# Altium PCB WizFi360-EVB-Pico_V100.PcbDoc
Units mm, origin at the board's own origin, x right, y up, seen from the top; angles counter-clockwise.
Board outline 75 x 21 mm, 2 copper layers (Top Layer, Bottom Layer); 60 components, 66 nets, 301 pads, 138 vias.
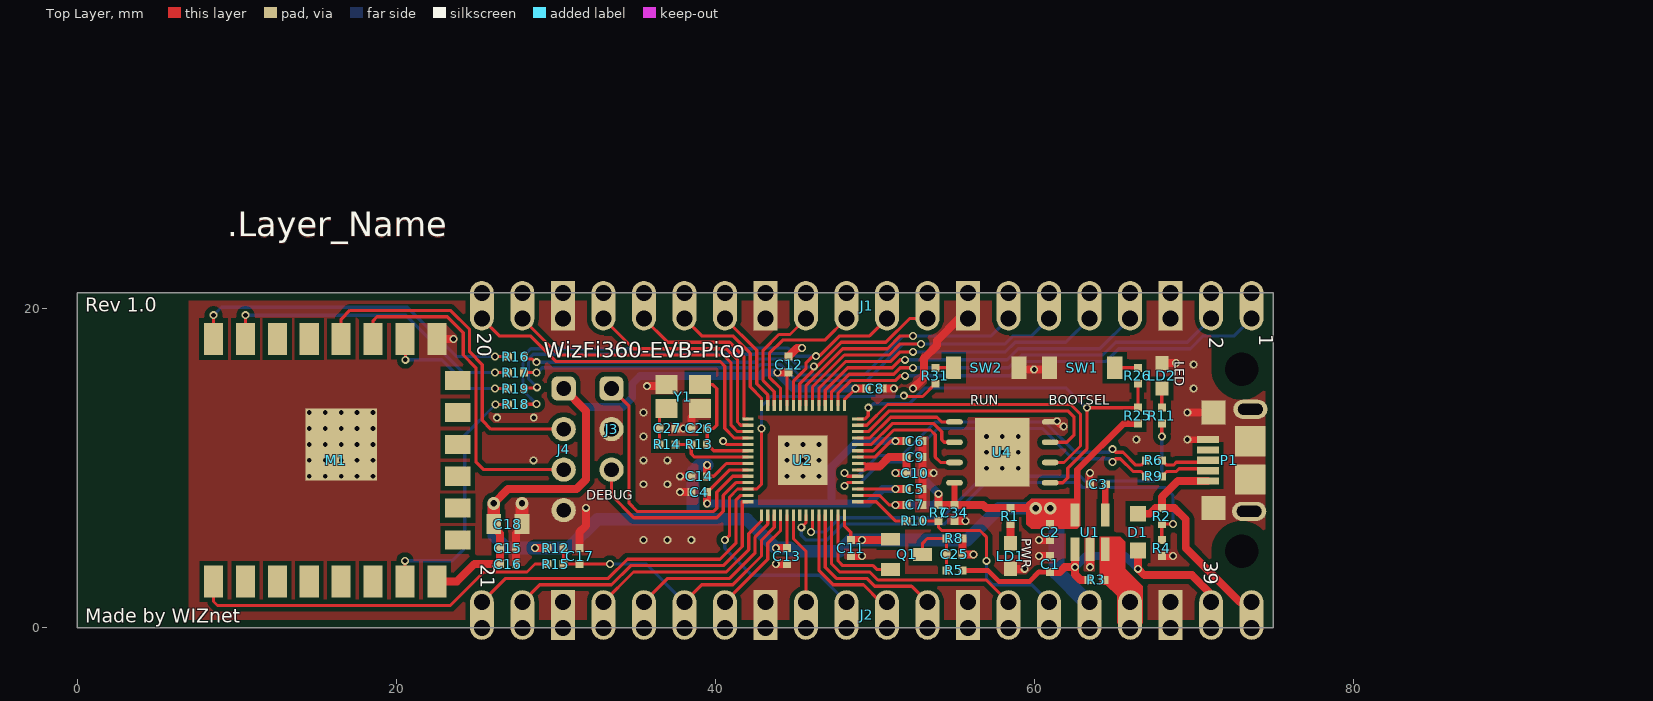
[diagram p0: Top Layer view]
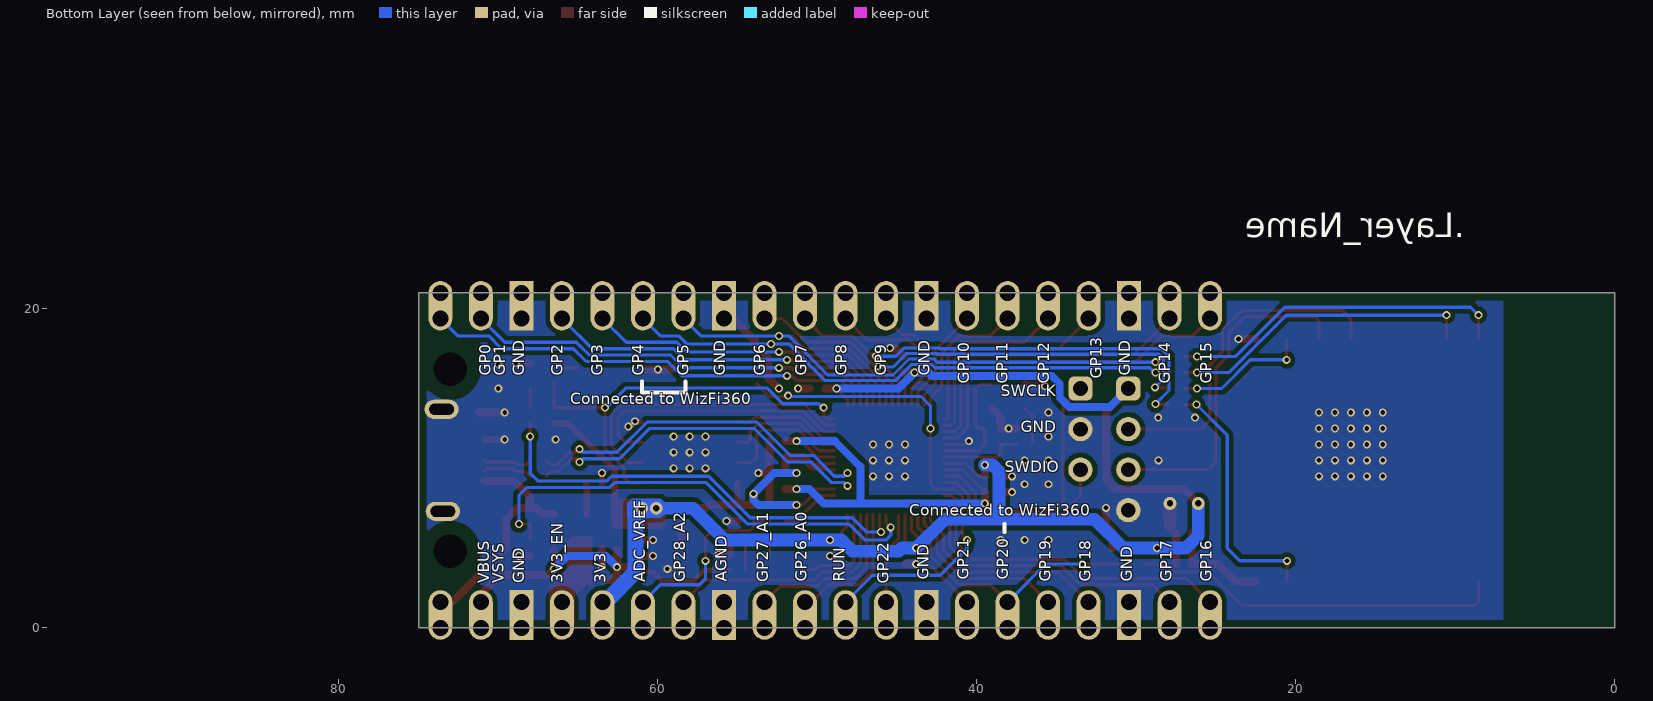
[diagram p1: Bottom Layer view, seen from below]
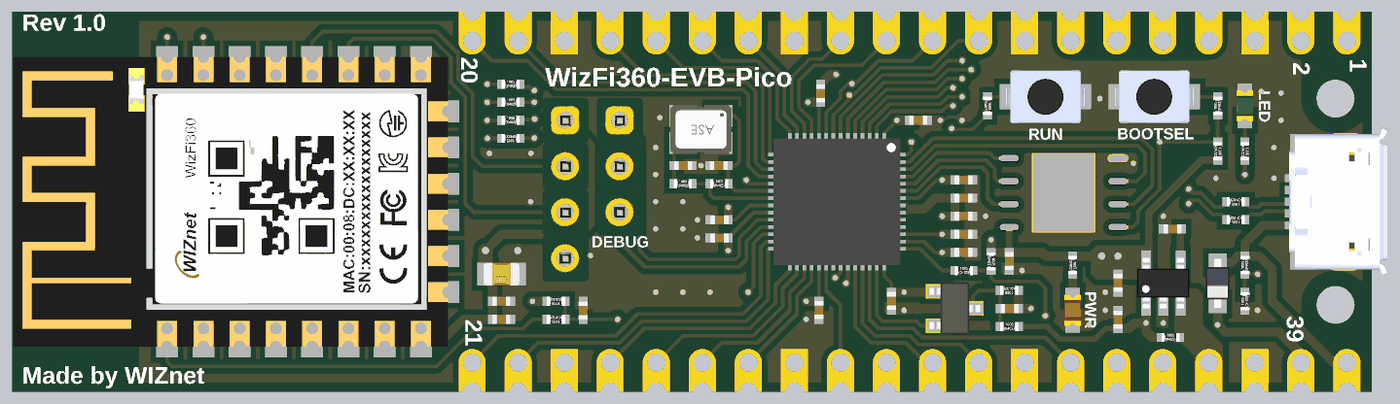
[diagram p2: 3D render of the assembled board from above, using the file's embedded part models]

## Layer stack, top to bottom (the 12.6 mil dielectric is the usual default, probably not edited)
Top Solder: solder mask 0.0102, Solder Resist, Dk 3.5
Top Layer: signal copper 0.0356
Dielectric1: prepreg 0.32, FR-4, Dk 4.8
Bottom Layer: signal copper 0.0356
Bottom Solder: solder mask 0.0102, Solder Resist, Dk 3.5

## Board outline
0,0 75,0 75,21 0,21

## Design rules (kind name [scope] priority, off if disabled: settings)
BoardOutlineClearance [All] p1: gap=0.5 ignorepadtopadclearanceinfootprint=FALSE
Clearance [All] p1: gap=0.15 ignorepadtopadclearanceinfootprint=FALSE except(0.3: Arc-Poly Track-Poly SMDPad-Poly THPad-Poly Via-Poly Fill-Poly Poly-Poly Poly-Region Poly-Text Poly-Hole)
DiffPairsRouting [All] p1: maxlimit=0.2 minlimit=0.2 mostfreqgap=0.2 toplayer_minwidth=0.2 toplayer_maxwidth=0.2 toplayer_prefwidth=0.2 bottomlayer_minwidth=0.2 bottomlayer_maxwidth=0.2 bottomlayer_prefwidth=0.2 maxuncoupledlength=15.24
HoleSize [All] p1: absolutevalues=TRUE maxlimit=4.064 minlimit=0.025 maxpercent=80.000 minpercent=20.000
PlaneClearance [All] p1: clearance=0.3
PlaneConnect [All] p1: planeconnectstyle=Direct reliefexpansion=0.508 reliefentries=4 reliefconductorwidth=0.254 reliefairgap=0.254
PolygonConnect [All] p1: connectstyle=Direct reliefconductorwidth=0.6 reliefentries=4 polygonreliefangle="45 Angle" airgapwidth=0.35
RoutingVias [All] p1: holewidth=0.3 width=0.5 viastyle="Through Hole" minholewidth=0.3 minwidth=0.5 maxholewidth=0.5 maxwidth=0.8
SolderMaskExpansion [All] p1: expansion=0 istentingtop=FALSE
Width [All] p1: maxlimit=2 minlimit=0.1 preferedwidth=0.2 minimp=50.000000 maximp=50.000000 favimp=50.000000
26 further rules are at their usual default settings.

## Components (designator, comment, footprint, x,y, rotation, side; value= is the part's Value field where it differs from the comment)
C1 "1uF" CAP-0402 61,4 r270 top
C2 "1uF" CAP-0402 61,6 r90 top
C3 "0.1uF" CAP-0402 64,9 r0 top
C4 "1uF" CAP-0402 39,8.5 r0 top
C5 "0.1uF" CAP-0402 52.5,8.7 r180 top
C6 "0.1uF" CAP-0402 52.5,11.7 r180 top
C7 "1uF" CAP-0402 52.5,7.7 r180 top
C8 "0.1uF" CAP-0402 50,15 r180 top
C9 "0.1uF" CAP-0402 52.5,10.7 r180 top
C10 "0.1uF" CAP-0402 52.5,9.7 r180 top
C11 "0.1uF" CAP-0402 48.5,5 r90 top
C12 "0.1uF" CAP-0402 44.6,16.5 r270 top
C13 "0.1uF" CAP-0402 44.5,4.5 r90 top
C14 "0.1uF" CAP-0402 39,9.5 r0 top
C15 "0.1uF" CAP-0402 27,5 r180 top
C16 "0.1uF" CAP-0402 27,4 r180 top
C17 "0.1uF" CAP-0402 31.5,4.5 r270 top
C18 "22uF" CAP-0805 27,6.5 r180 top
C25 "0.1uF" CAP-0402 55,4.6 r0 top
C26 "15pF" CAP-0402 39,12.5 r180 top
C27 "15pF" CAP-0402 37,12.5 r0 top
C34 "0.1uF" CAP-0402 55,7.2 r90 top
D1 "BAT60A" SOD-323(1-C,2-A) 66.5,6 r90 top
J1 "2.54mm 1x20 Pin Header DIP" IDC-1X20 73.63,19.39 r180 top
J2 "2.54mm 1x20 Pin Header DIP" IDC-1X20 25.37,1.61 r0 top
J3 "2.54mm 1x3 Pin Header DIP" IDC-1X3 33.5,15 r270 top
J4 "2.54mm 1x4 Pin Header DIP" IDC-1X4 30.5,15 r270 top
LD1 "Red" LED-0603-RED 58.5,4.5 r270 top
LD2 "Green" LED-0603-GREEN 68,15.8 r90 top
M1 "WizFi360" WizFi360-PA 16.2,10.5 r90 top
P1 "Micro USB" "MICRO 5P B DBX 6.4" 75,10.5 r180 top
Q1 "Q-2N7002" SOT23-3L 52,4.6 r270 top
R1 "470R" RES-0402 58.5,7 r270 top
R2 "5.6K" RES-0402 68,7 r90 top
R3 "100K" RES-0402 63.9,3 r0 top
R4 "10K" RES-0402 68,5 r90 top
R5 "200K" RES-0402 55,3.6 r0 top
R6 "27R" RES-0402 67.5,10.5 r180 top
R7 "200R" RES-0402 54,7.2 r270 top
R8 "100K" RES-0402 55,5.6 r180 top
R9 "27R" RES-0402 67.5,9.5 r180 top
R10 "1R" RES-0402 52.5,6.7 r0 top
R11 "470R" RES-0402 68,13.3 r270 top
R12 "4.7K" RES-0402 30,5 r180 top
R13 "NC" RES-0402 39,11.5 r0 top
R14 "1K" RES-0402 37,11.5 r0 top
R15 "1K" RES-0402 30,4 r180 top
R16 "1K" RES-0402 27.5,17 r0 top
R17 "1K" RES-0402 27.5,16 r0 top
R18 "1K" RES-0402 27.5,14 r180 top
R19 "1K" RES-0402 27.5,15 r0 top
R25 "NC" RES-0402 66.5,13.3 r270 top
R26 "1K" RES-0402 66.5,15.8 r90 top
R31 "1K" RES-0402 53.8,15.8 r270 top
SW1 "PTS820" PTS820 63,16.3 r180 top
SW2 "PTS820" PTS820 57,16.3 r0 top
U1 "LM8805SF5-33V" SOT-23-5L 63.5,6 r90 top
U2 "RP2040" QFN56(0.4/7X7) 45.5,10.5 r270 top
U4 "W25Q16JVZPIM" WSON8(6X5_1.27) 58,11 r180 top
Y1 "12MHz" OSC-TZ1067B 38,14.5 r180 top

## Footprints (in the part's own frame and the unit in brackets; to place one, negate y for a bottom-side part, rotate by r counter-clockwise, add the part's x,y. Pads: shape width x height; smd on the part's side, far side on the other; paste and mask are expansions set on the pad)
CAP-0402 [mm]
  rect 0.5x0.5 smd: 1(-0.5,0) 2(0.5,0)
  body extent -0.48,-0.25 0.52,0.25, height 0.6
CAP-0805 [mil]
  rect 36x49 smd: 1(-35,0)
  rect 35.43x49 smd: 2(35,0)
  body extent -39,-25 40,25, height 31
IDC-1X3 [mil]
  rrect50% 60x60 hole 36: 1(0,0)
  round 60 hole 36: 2(100,0) 3(200,0)
  body extent -49,-49 251,51, height 336
IDC-1X4 [mil]
  rrect50% 60x60 hole 36: 1(0,0)
  round 60 hole 36: 2(100,0) 3(200,0) 4(300,0)
  body extent -49,-49 351,51, height 336
IDC-1X20 [mm]
  oval 1.5x2.5 hole 1 copper offset 0,-0.5: 1(0,0) 2(2.54,0) 4(7.62,0) 5(10.16,0) 6(12.7,0) 7(15.24,0) 9(20.32,0) 10(22.86,0) 11(25.4,0) 12(27.94,0) 14(33.02,0) 15(35.56,0) 16(38.1,0) 17(40.64,0) 19(45.72,0) 20(48.26,0)
  oval 1.5x2.5 hole 1 copper offset 0,0.5: 1(0,-1.61) 2(2.54,-1.61) 4(7.62,-1.61) 5(10.16,-1.61) 6(12.7,-1.61) 7(15.24,-1.61) 9(20.32,-1.61) 10(22.86,-1.61) 11(25.4,-1.61) 12(27.94,-1.61) 14(33.02,-1.61) 15(35.56,-1.61) 16(38.1,-1.61) 17(40.64,-1.61) 19(45.72,-1.61) 20(48.26,-1.61)
  rect 1.5x2.5 hole 1 copper offset 0,0.5: 3(5.08,-1.61) 8(17.78,-1.61) 13(30.48,-1.61) 18(43.18,-1.61)
  rect 1.5x2.5 hole 1 copper offset 0,-0.5: 3(5.08,0) 8(17.78,0) 13(30.48,0) 18(43.18,0)
LED-0603-GREEN [mm] "LED-0603-GREEN"
  rect 0.89x0.82 smd: 1(-0.8,0) 2(0.8,0)
  body extent -0.85,-0.45 0.85,0.45, height 0.9
LED-0603-RED [mm] "LED-0603-RED"
  rect 0.89x0.82 smd: 1(-0.8,0) 2(0.8,0)
  body extent -0.85,-0.45 0.85,0.45, height 0.9
"MICRO 5P B DBX 6.4" [mm]
  rect 1.38x0.45 smd: 1(4.11,1.3) 2(4.11,0.65) 3(4.11,0) 4(4.11,-0.65) 5(4.11,-1.3)
  oval 2.15x1.2 hole 0.7 slot 1.55 at 0 deg: 6(1.524,3.2) 7(1.45,-3.2)
  rect 1.9x1.9 smd: 8(1.45,1.2) 9(1.45,-1.2)
  rect 1.5x1.5 smd: 10(3.75,-3) 11(3.75,3)
  body extent -0.88,-4.1 4.55,4.1, height 2.68
OSC-TZ1067B [mm]
  rect 1.4x1.2 smd: 1(-1.05,-0.75) 2(1.05,-0.75) 3(1.05,0.75) 4(-1.05,0.75)
  body extent -1.7,-1.35 1.7,1.35, height 1.06
PTS820 [mm]
  rect 0.95x1.4 smd: 1(-2.05,0) 2(2.05,0)
  body extent -2.18,-1.45 2.18,1.45, height 1.7
QFN56(0.4/7X7) [mm]
  rect 0.7x0.2 smd: 1(-3.44,2.6) 2(-3.44,2.2) 3(-3.44,1.8) 4(-3.44,1.4) 5(-3.44,1) 6(-3.44,0.6) 7(-3.44,0.2) 8(-3.44,-0.2) 9(-3.44,-0.6) 10(-3.44,-1) 11(-3.44,-1.4) 12(-3.44,-1.8) 13(-3.44,-2.2) 14(-3.44,-2.6) 29(3.44,-2.6) 30(3.44,-2.2) 31(3.44,-1.8) 32(3.44,-1.4) 33(3.44,-1) 34(3.44,-0.6) 35(3.44,-0.2) 36(3.44,0.2) 37(3.44,0.6) 38(3.44,1) 39(3.44,1.4) 40(3.44,1.8) 41(3.44,2.2) 42(3.44,2.6)
  rect 0.2x0.7 smd: 15(-2.6,-3.44) 16(-2.2,-3.44) 17(-1.8,-3.44) 18(-1.4,-3.44) 19(-1,-3.44) 20(-0.6,-3.44) 21(-0.2,-3.44) 22(0.2,-3.44) 23(0.6,-3.44) 24(1,-3.44) 25(1.4,-3.44) 26(1.8,-3.44) 27(2.2,-3.44) 28(2.6,-3.44) 43(2.6,3.44) 44(2.2,3.44) 45(1.8,3.44) 46(1.4,3.44) 47(1,3.44) 48(0.6,3.44) 49(0.2,3.44) 50(-0.2,3.44) 51(-0.6,3.44) 52(-1,3.44) 53(-1.4,3.44) 54(-1.8,3.44) 55(-2.2,3.44) 56(-2.6,3.44)
  rect 3.1x3.1 smd: 57(0,0)
  body extent -3.5,-3.5 3.5,3.5, height 0.8
RES-0402 [mm]
  rect 0.5x0.5 smd: 1(-0.5,0) 2(0.5,0)
  body extent -0.5,-0.25 0.5,0.25, height 0.35
SOD-323(1-C,2-A) [mm]
  rect 1x1 smd: 1(-1.15,0) 2(1.15,0)
  body extent -1.35,-0.67 1.35,0.68, height 0.79
SOT23-3L [mm]
  rect 0.8x1.2 smd paste-0.07: 1(-0.95,-1) 2(0.95,-1) 3(0,1)
  body extent -1.45,-1.4 1.45,1.4, height 1.28
SOT-23-5L [mm]
  rect 1.45x0.55 smd: 1(-1.075,0.95) 2(-1.075,0) 3(-1.075,-0.95) 4(1.075,-0.95) 5(1.075,0.95)
  body extent -1.4,-1.45 1.4,1.45, height 1.45
WizFi360-PA [mm]
  rect 2x1.2 smd: 1(-7.6,7.65) 2(-7.6,5.65) 3(-7.6,3.65) 4(-7.6,1.65) 5(-7.6,-0.35) 6(-7.6,-2.35) 7(-7.6,-4.35) 8(-7.6,-6.35) 15(7.6,-6.35) 16(7.6,-4.35) 17(7.6,-2.35) 18(7.6,-0.35) 19(7.6,1.65) 20(7.6,3.65) 21(7.6,5.65) 22(7.6,7.65)
  rect 1.2x1.6 smd: 9(-5,-7.65) 10(-3,-7.65) 11(-1,-7.65) 12(1,-7.65) 13(3,-7.65) 14(5,-7.65)
  rect 4.5x4.5 smd: 23(1,-0.35)
  body extent -8,-7.85 8,16.15, height 2.97
WSON8(6X5_1.27) [mm]
  oval 1.05x0.35 smd mask+0.05: 1(-3,1.905) 2(-3,0.635) 3(-3,-0.635) 4(-3,-1.905) 5(3,-1.905) 6(3,-0.635) 7(3,0.635) 8(3,1.905)
  rect 3.4x4.3 smd mask+0.05: 9(0,0)
  body extent -3,-2.5 3,2.5, height 0.8

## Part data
C1 C2 C3 C4 C5 C6 C7 C8 C9 C10 C11 C12 C13 C14 C15 C16 C17 C25 C26 C27 C34: library part CAP-0402, "Ceramic CAP 0402(1005)"
C18: library part CAP-0805, "Ceramic CAP 0805(2012)"
D1: library part DIODE-BAT60A, "Silicon Schottky Diode"
LD1 LD2: library part LED-0603, "LED-0603"
P1: library part "Micro USB 5P DBX6.4", "Micro USB B Connector SMD"
Q1: "N-Channel 60-V (D-S) MOSFET"
R1 R2 R3 R4 R5 R6 R7 R8 R9 R10 R11 R12 R13 R14 R15 R16 R17 R18 R19 R25 R26 R31: library part RES-0402, "RES-0402"
SW1 SW2: library part ITS-1107(SMD), "TACT Switch (SMD)"
U1: "600mA CMOS LDO Regulator"
U2: "Raspverry Pi, Dual ARM Cortex-M0+ @ 133MHz"
U4: "3V 16M-BIT / SERIAL FLASH MEMORY WITH / DUAL/QUAD SPI, QPI & DTR"
Y1: library part OSC-TZ1067B-12MHz, "X-tal 12MHz,3.2x2.5 SMD, CL=20pF"

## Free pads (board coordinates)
  round 0 hole 2.1 unplated: 0(73,4.8) 0(73,16.2)
  round 0 on Mech16 paste+0 mask+0: 1(93.2,16.4) 1(96.4,35.9)

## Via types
v1: diameter 0.5, hole 0.3, Top Layer to Bottom Layer, tented both sides, 134 vias
v2: diameter 0.8, hole 0.4, Top Layer to Bottom Layer, tented both sides, 4 vias

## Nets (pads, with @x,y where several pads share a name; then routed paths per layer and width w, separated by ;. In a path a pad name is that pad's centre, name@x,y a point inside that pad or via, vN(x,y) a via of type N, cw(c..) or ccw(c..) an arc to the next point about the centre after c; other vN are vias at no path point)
1V1: C4.2 C5.2 C6.2 U2.23 U2.45 U2.50 | length 29.5
  Top Layer w0.2: C4.2 40.9,9.9 U2.23 ; U2.45 v1(51.3,8.7) ; U2.50 50,10.7 51,11.7 v1(51.3,11.7)
  Top Layer w0.5: v1(39.5,7.8) C4.2 ; v1(51.3,8.7) C5.2 ; v1(51.3,11.7) C6.2
  Bottom Layer w0.5: v1(39.5,7.8) 47.3,7.8 ; v1(51.3,8.7) 50.5,8.7 49.6,7.8 47.3,7.8 ; v1(51.3,11.7) 48.9,11.7 47.3,10.1 47.3,7.8
3V3: C2.2 C7.2 C8.2 C9.2 C10.2 C11.2 C12.2 C13.2 C14.2 C15.2 C16.2 C18.2 C34.2 J2.16 J4.1 M1.8 Q1.1 R1.1 R7.1 R12.2 R25.2 U1.5 U2.1 U2.10 U2.22 U2.33 U2.42 U2.44 U2.48 U2.49 U4.8 | length 139.8
  Top Layer w0.2: C14.2 39.9,9.5 40.7,10.3 U2.22 ; C13.2 U2.33 ; U2.10 44.5,15.9 C12.2 ; U2.42 48.1,6.4 48.5,6 C11.2 ; U2.1 48.1,14.3 v1(48.8,15) ; U2.44 50.3,8.3 50.9,7.7 v1(51.3,7.7) ; U2.48 49.4,9.9 49.6,10.1 49.4,10.3 U2.49
  Top Layer w0.35: C34.2 U4.8
  Top Layer w0.4: U1.5 62.7,7.225 62.7,9.9 65.6,12.8 R25.2
  Top Layer w0.5: M1.8 23.8,2.9 24.9,4 C16.2 C15.2 26.5,5.9 26.111,6.289 C18.2 ; v2(26.111,7.8) 27.011,8.7 31.3,8.7 31.9,9.3 31.9,13.6 J4.1 ; v1(28.7,5) R12.2 ; C14.2 v1(39.5,10.2) ; v1(43.8,5) C13.2 ; v1(43.9,16) C12.2 ; C11.2 v1(49.2,5.5) 50.95,5.5 Q1.1 ; v1(48.8,15) C8.2 ; 49.6,10.1 50.3,10.1 50.9,10.7 C9.2 ; v1(51.3,7.7) C7.2 ; v1(51.3,9.7) C10.2 C9.2@52,10.5 ; v1(54,8.4) R7.1 C34.2 56.8,7.7 57,7.5 R1.1 v2(60.1,7.5)
  Top Layer w0.8: C18.2 v2(26.111,7.8)
  Bottom Layer w0.5: J4.1 31.662,13.838 34.204,13.838 34.8,14.434 34.8,15.3 35.3,15.8 42.825,15.8 43.025,16 v1(43.9,16) 44.9,15 v1(48.8,15) ; v1(51.3,7.7) 53.7,7.7 54,8 v1(54,8.4) 52.7,9.7 v1(51.3,9.7)
  Bottom Layer w0.8: v2(26.111,7.8) 26.111,5.789 26.9,5 v1(28.7,5) 30.8,5 32.6,6.8 38.6,6.8 ; v1(39.5,10.2) 39,10.2 38.6,9.8 38.6,6.8 ; v2(60.1,7.5) 57.8,7.5 55.8,5.5 v1(49.2,5.5) 48.5,5.5 47.8,4.8 44.9,4.8 44.7,5 v1(43.8,5) 42,6.8 38.6,6.8 ; v2(61,7.5) 61.5,7.5
  Bottom Layer w1: 61.4,7.4 61.4,3.5 63.29,1.61 J2.16@63.47,1.61
3V3_EN: J2.17 R3.2 U1.3
ADC_VREF: J2.15 R7.2 R10.2 | length 11.8
  Top Layer w0.2: R10.2 R7.2 54,6.3 54.2,6.1 56.6,6.1 57,5.7 v1(57,4.2)
  Bottom Layer w0.2: v1(57,4.2) 57,3.1 57.4,2.7 59.84,2.7 J2.15@60.93,1.61
GND: C1.1 C2.1 C3.1 C4.1 C5.1 C6.1 C7.1 C8.1 C9.1 C10.1 C11.1 C12.1 C13.1 C14.1 C15.1 C16.1 C17.1 C18.1 C25.2 C26.2 C27.2 C34.1 J1.3 J1.8 J1.13 J1.18 J2.3 J2.8 J2.13 J2.18 J3.2 J4.4 LD1.2 LD2.2 M1.15 M1.23 P1.5 P1.6 P1.7 P1.8 P1.9 P1.10 P1.11 R4.1 R8.1 SW1.2 SW2.2 U1.2 U2.19 U2.57 U4.4 U4.9 Y1.2 Y1.4 | length 42.6
  Top Layer w0.2: v1(40.5,11.7) 40.7,11.5 U2.19
  Top Layer w0.3: U4.4 61.38,12.905 v1(61.425,12.95) ; U4.4@61.364,12.905 61.605,12.663 61.812,12.663 v1(61.85,12.625)
  Top Layer w0.4: C3.1 v1(63.5,9.7) ; v1(69.6,11.8) P1.5
  Top Layer w0.5: M1.15 v1(23.6,18.1) ; C16.1 C15.1 27.5,5.9 27.889,6.289 C18.1 ; C17.1 31.5,6 31.9,6.4 v1(31.9,7.525) ; v1(35.725,15.15) 36.85,15.15 Y1.2 ; C27.2 v1(38,12.5) C26.2 38.5,13.2 Y1.4 ; v1(37.8,8.5) C4.1 ; v1(37.8,9.5) C14.1 ; v1(43.8,4) C13.1 ; C12.1 45.134,17.534 v1(45.45,17.534) ; C11.1 v1(49.2,4.5) ; C8.1 v1(51.2,15) ; v1(52.4,15) 53.1,15.7 53.1,16.9 53.9,17.7 53.9,18 55.29,19.39 J1.8@55.85,19.39 ; C7.1 C5.1 C10.1 ; C6.1 C9.1 C10.1 ; v1(53.7,9.7) C10.1 ; C34.1 v1(55.7,6.7) ; R8.1 C25.2 v1(56.2,4.6) ; LD1.2 v1(59.4,3.7) ; SW2.2 59.15,16.2 v1(60,16.2) 60.85,16.2 SW1.2 ; v1(60.3,4.5) C1.1 ; v1(60.3,5.5) C2.1 ; v1(63.5,3.8) U1.2 ; R4.1 v1(68.7,4.5) ; LD2.2 v1(68.9,16.6) ; v1(69.6,13.5) P1.10
  Top Layer w0.8: C18.1 v2(27.889,7.8)
  other v1: 35.5,5.5 37,5.5 38.5,5.5 35.5,9 37,9 14.55,9.5 15.55,9.5 16.55,9.5 17.55,9.5 18.55,9.5 44.5,9.5 45.5,9.5 46.5,9.5 57,10 58,10 59,10 14.55,10.5 15.55,10.5 16.55,10.5 17.55,10.5 18.55,10.5 28.6,10.5 35.5,10.5 37,10.5 44.5,10.5 45.5,10.5 46.5,10.5 57,11 58,11 59,11 14.55,11.5 15.55,11.5 16.55,11.5 17.55,11.5 18.55,11.5 44.5,11.5 45.5,11.5 46.5,11.5 66.4,11.8 35.5,12 57,12 58,12 59,12 14.55,12.5 15.55,12.5 16.55,12.5 17.55,12.5 18.55,12.5 26.325,13.175 28.625,13.175 14.55,13.5 15.55,13.5 16.55,13.5 17.55,13.5 18.55,13.5 35.5,13.5 70,15 70,16.5
GPIO0: J1.1 U2.2 | length 28.6
  Top Layer w0.2: U2.2 47.7,14.7 48.5,15.5 51.3,15.5 51.6,15.8 v1(51.9,15.8)
  Bottom Layer w0.2: v1(51.9,15.8) 58.5,15.8 59.4,16.7 64.5,16.7 65.3,17.5 69.8,17.5 70.6,18.3 72.54,18.3 J1.1@73.63,19.39
GPIO1: J1.2 U2.3 | length 26.6
  Top Layer w0.2: U2.3 47.3,14.8 48.4,15.9 51.2,15.9 51.6,16.3 v1(52.4,16.3)
  Bottom Layer w0.2: v1(52.4,16.3) 58.4,16.3 59.2,17.1 64.3,17.1 65.1,17.9 69.6,17.9 J1.2@71.09,19.39
GPIO2: J1.4 U2.4 | length 21.9
  Top Layer w0.2: U2.4 46.9,14.9 48.3,16.3 51.1,16.3 51.6,16.8 v1(51.9,16.8)
  Bottom Layer w0.2: v1(51.9,16.8) 58.3,16.8 59,17.5 64.12,17.5 J1.4@66.01,19.39
GPIO3: J1.5 U2.5 | length 19.8
  Top Layer w0.2: U2.5 46.5,15 48.2,16.7 51,16.7 51.6,17.3 v1(52.4,17.3)
  Bottom Layer w0.2: v1(52.4,17.3) 58.2,17.3 58.8,17.9 61.98,17.9 J1.5@63.47,19.39
GPIO4: J1.6 R17.2 U2.6 | length 44.2
  Top Layer w0.2: R17.2 v1(28.8,16) ; U2.6 46.1,15.1 48.1,17.1 50.9,17.1 51.6,17.8 v1(52.9,17.8)
  Bottom Layer w0.2: v1(28.8,16) 28.857,16 29.157,16.3 42.618,16.3 42.818,16.5 44.107,16.5 45.107,15.5 49.495,15.5 51.795,17.8 v1(52.9,17.8) 58.175,17.8 58.675,18.3 59.84,18.3 J1.6@60.93,19.39
GPIO5: J1.7 R16.2 U2.7 | length 41.7
  Top Layer w0.2: R16.2 28.15,16.85 28.519,16.85 28.719,16.65 v1(28.8,16.65) ; U2.7 45.7,15.2 48,17.5 50.8,17.5 51.6,18.3 v1(52.4,18.3)
  Bottom Layer w0.2: v1(28.8,16.65) 42.473,16.65 42.673,16.85 44.252,16.85 45.252,15.85 49.35,15.85 51.8,18.3 52.3,18.3 57.3,18.3 J1.7@58.39,19.39
GPIO6: J1.9 R19.2 U2.8 | length 32.4
  Top Layer w0.2: R19.2 28.037,15.037 28.787,15.037 v1(28.825,15.075) ; U2.8 45.3,15.3 46.127,16.127 46.127,16.334 46.19,16.397 46.403,16.397 47.9,17.895 47.9,17.9 50.7,17.9 52.19,19.39 J1.9@53.31,19.39
  Bottom Layer w0.2: v1(28.825,15.075) 28.3,15.6 28.3,16.857 28.593,17.15 42.478,17.15 42.528,17.2 44.397,17.2 45.247,16.35 46.143,16.35 v1(46.184,16.391)
GPIO7: J1.10 R18.1 U2.9 | length 32.2
  Top Layer w0.2: R18.1 28.012,14.012 28.787,14.012 v1(28.8,14.025) ; U2.9 44.9,15.446 45.684,16.23 45.684,16.598 46.054,16.968 46.266,16.968 46.381,17.083 46.583,17.083 47.8,18.3 49.68,18.3 J1.10@50.77,19.39
  Bottom Layer w0.2: v1(28.8,14.025) 27.95,14.875 27.95,17.002 28.448,17.5 42.333,17.5 42.383,17.55 44.542,17.55 45.066,17.026 v1(46.324,17.026)
GPIO8: J1.11 U2.11 | length 9.3
  Top Layer w0.2: U2.11 44.1,15 43.4,15.7 43.4,17.2 44.24,18.04 46.88,18.04 J1.11@48.23,19.39
GPIO9: J1.12 U2.12 | length 7.3
  Top Layer w0.2: U2.12 43.7,14.8 43,15.5 43,17.4 43.99,18.39 44.69,18.39 J1.12@45.69,19.39
GPIO10: J1.14 U2.13 | length 6.6
  Top Layer w0.2: J1.14@40.61,19.39 42.6,17.4 42.6,15.3 43.3,14.6 U2.13
GPIO11: J1.15 U2.14 | length 8.6
  Top Layer w0.2: J1.15@38.07,19.39 39.16,18.3 41.1,18.3 42.2,17.2 42.2,15.1 42.9,14.4 U2.14
GPIO12: J1.16 U2.15 | length 11.4
  Top Layer w0.2: J1.16@35.53,19.39 37.02,17.9 40.9,17.9 41.8,17 41.8,13.1 U2.15
GPIO13: J1.17 U2.16 | length 14.1
  Top Layer w0.2: J1.17@32.99,19.39 34.88,17.5 40.7,17.5 41.4,16.8 41.4,12.9 41.6,12.7 U2.16
GPIO14: J1.19 U2.17 | length 19.4
  Top Layer w0.2: J1.19@27.91,19.39 30.2,17.1 40.5,17.1 41,16.6 41,12.7 41.4,12.3 U2.17
GPIO15: J1.20 U2.18 | length 22.1
  Top Layer w0.2: J1.20@25.37,19.39 26.46,18.3 28.4,18.3 30,16.7 40.3,16.7 40.6,16.4 40.6,12.5 41.2,11.9 U2.18
GPIO16: J2.1 U2.27 | length 21
  Top Layer w0.2: J2.1@25.37,1.61 26.86,3.1 33.3,3.1 34.5,4.3 40.3,4.3 41.3,5.3 41.3,8 41.6,8.3 U2.27
GPIO17: J2.2 U2.28 | length 18.4
  Top Layer w0.2: J2.2@27.91,1.61 29,2.7 33.5,2.7 34.7,3.9 40.5,3.9 41.7,5.1 41.7,7.9 U2.28
GPIO18: J2.4 U2.29 | length 13
  Top Layer w0.2: J2.4@32.99,1.61 34.88,3.5 40.7,3.5 42.1,4.9 42.1,5.9 42.9,6.7 U2.29
GPIO19: J2.5 U2.30 | length 10.9
  Top Layer w0.2: J2.5@35.53,1.61 37.02,3.1 40.9,3.1 42.5,4.7 42.5,5.7 43.3,6.5 U2.30
GPIO20: C17.2 J2.6 R12.1 R15.1 U2.31 | length 18.5
  Top Layer w0.2: R12.1 R15.1 C17.2 v1(33.4,4) ; J2.6@38.07,1.61 39.16,2.7 41.1,2.7 42.9,4.5 42.9,5.5 43.7,6.3 U2.31
  Bottom Layer w0.2: v1(33.4,4) 35.68,4 J2.6@38.07,1.61
GPIO21: J2.7 U2.32 | length 6.9
  Top Layer w0.2: J2.7@40.61,1.61 43.3,4.3 43.3,5.3 44.1,6.1 U2.32
GPIO22: J2.9 U2.34 | length 5.8
  Top Layer w0.2: U2.34 44.9,5.6 45.69,4.81 J2.9@45.69,1.61
GPIO24: R2.1 R4.2 U2.36 | length 30.1
  Top Layer w0.2: v1(45.4,6.3) 45.7,6.6 U2.36 ; R4.2 R2.1 v1(68.7,6.5)
  Bottom Layer w0.2: v1(45.4,6.3) 45.4,5.8 45.7,5.5 47,5.5 48,6.5 54.366,6.5 56.966,9.1 62.7,9.1 63,8.8 68.2,8.8 68.7,8.3 v1(68.7,6.5)
GPIO25: R11.2 U2.37 | length 28
  Top Layer w0.2: v1(46,6) 46.1,6.1 U2.37 ; v1(68,12) R11.2
  Bottom Layer w0.2: v1(46,6) 46.9,6 47.8,6.9 54.2,6.9 56.8,9.5 62.9,9.5 63.2,9.2 67.5,9.2 68,9.7 v1(68,12)
GPIO26/ADC0: J2.11 U2.38 | length 8.6
  Top Layer w0.2: U2.38 46.5,3.6 47.4,2.7 49.3,2.7 50.39,1.61 J2.11@50.77,1.61
GPIO27/ADC1: J2.12 U2.39 | length 10.6
  Top Layer w0.2: U2.39 46.9,3.8 47.6,3.1 49.5,3.1 49.99,2.61 52.31,2.61 J2.12@53.31,1.61
GPIO28/ADC2: J2.14 U2.40 | length 15.1
  Top Layer w0.2: U2.40 47.3,4 47.8,3.5 49.7,3.5 50.2,3 57,3 J2.14@58.39,1.61
GPIO29/ADC3: Q1.2 U2.41 | length 6.4
  Top Layer w0.2: U2.41 47.7,4.2 48,3.9 49.9,3.9 50.15,3.65 Q1.2
NetC3_2: C3.2 U1.4 | length 1.9
  Top Layer w0.4: U1.4 64.45,8.95 C3.2
NetC25_1: C25.1 Q1.3 R5.1 R8.2 | length 4.3
  Top Layer w0.2: Q1.3 53,5.3 53.3,5.6 R8.2 C25.1 R5.1
NetC27_1: C27.1 R14.1 Y1.3 | length 2.4
  Top Layer w0.2: R14.1 C27.1 36.5,13.3 Y1.3
NetJ4_2: J4.2 M1.18 | length 21.4
  Top Layer w0.2: M1.18 16.55,19.35 17.1,19.9 23.4,19.9 24.6,18.7 24.6,17.3 25.4,16.5 25.4,13 25.94,12.46 J4.2
NetJ4_3: J4.3 M1.17 | length 21.4
  Top Layer w0.2: M1.17 18.55,19.25 18.8,19.5 23.2,19.5 24.2,18.5 24.2,17.1 25,16.3 25,10.4 25.48,9.92 J4.3
NetLD1_1: LD1.1 R1.2 | length 1.2
  Top Layer w0.5: LD1.1 R1.2
NetLD2_1: LD2.1 R11.1 | length 1.2
  Top Layer w0.2: R11.1 LD2.1
NetM1_1: M1.1 R15.2 | length 23.4
  Top Layer w0.2: M1.1 8.55,1.65 8.8,1.4 23.4,1.4 25.5,3.5 28.2,3.5 28.7,4 R15.2
NetM1_7: M1.7 R18.2 | length 16
  Top Layer w0.2: M1.7 v1(20.55,4.2) ; v1(26.225,14) R18.2
  Bottom Layer w0.2: v1(20.55,4.2) 23.504,4.2 24.3,4.996 24.3,12.075 v1(26.225,14)
NetM1_16: M1.16 R19.1 | length 8.5
  Top Layer w0.2: M1.16 20.575,18.075 v1(20.575,16.8) ; v1(26.2,15) R19.1
  Bottom Layer w0.2: v1(20.575,16.8) 22.85,16.8 24.65,15 v1(26.2,15)
NetM1_21: M1.21 R17.1 | length 19.4
  Top Layer w0.2: M1.21 v1(10.55,19.6) ; v1(26.2,16) R17.1
  Bottom Layer w0.2: v1(10.55,19.6) 20.6,19.6 24.2,16 v1(26.2,16)
NetM1_22: M1.22 R16.1 | length 21.4
  Top Layer w0.2: M1.22 v1(8.55,19.6) ; v1(26.2,17) R16.1
  Bottom Layer w0.2: v1(8.55,19.6) 9.05,20.1 20.7,20.1 23.8,17 v1(26.2,17)
NetR6_2: R6.2 U2.47 | length 22.7
  Top Layer w0.2: v1(48.1,9.7) 48.3,9.5 U2.47 ; v1(64.9,11.2) 65.1,11 65.566,11 66.366,10.2 66.7,10.2 R6.2
  Bottom Layer w0.2: v1(48.1,9.7) 48.3,9.5 48.934,9.5 50.234,10.8 51.7,10.8 53.8,12.9 60.666,12.9 62.566,11 64.7,11 v1(64.9,11.2)
NetR9_2: R9.2 U2.46 | length 22.7
  Top Layer w0.2: v1(48.1,8.9) 48.3,9.1 U2.46 ; v1(64.9,10.4) 65.1,10.6 65.4,10.6 66.2,9.8 66.7,9.8 R9.2
  Bottom Layer w0.2: v1(48.1,8.9) 48.3,9.1 49.1,9.1 50.4,10.4 51.866,10.4 53.966,12.5 60.5,12.5 62.4,10.6 64.7,10.6 v1(64.9,10.4)
NetR10_1: R10.1 U2.43 | length 3.6
  Top Layer w0.2: U2.43 50.1,7.9 51.3,6.7 R10.1
NetR26_2: R26.2 SW1.1 | length 1.4
  Top Layer w0.2: SW1.1 R26.2
NetR31_1: R31.1 SW2.1 | length 1.2
  Top Layer w0.2: R31.1 SW2.1
QSPI1_SCLK: U2.52 U4.6 | length 7.4
  Top Layer w0.2: U2.52 49.8,11.5 51.1,12.8 53.7,12.8 54.2,12.3 54.2,11.8 54.365,11.635 U4.6
QSPI1_SD0: U2.53 U4.5 | length 6.7
  Top Layer w0.2: U2.53 49.7,11.9 51,13.2 53.905,13.2 54.2,12.905 U4.5
QSPI1_SD1: U2.55 U4.2 | length 19.1
  Top Layer w0.2: U2.55 49.5,12.7 50.8,14 62.3,14 62.9,13.4 62.9,11.4 61.865,10.365 U4.2
QSPI1_SD2: U2.54 U4.3 | length 17.1
  Top Layer w0.2: U2.54 49.6,12.3 50.9,13.6 62.1,13.6 62.5,13.2 62.5,12.1 62.035,11.635 U4.3
QSPI1_SD3: U2.51 U4.7 | length 8.3
  Top Layer w0.2: U2.51 49.9,11.1 51.2,12.4 53.5,12.4 53.8,12.1 53.8,10.7 54.135,10.365 U4.7
QSPI1_SS_N: R25.1 R26.1 U2.56 U4.1 | length 26.8
  Top Layer w0.2: U2.56 49.4,13.1 49.6,13.3 v1(49.6,13.8) ; U4.1 61.795,9.095 62.1,9.4 62.1,10 63.3,11.2 v1(63.3,13.8) R25.1 R26.1
  Bottom Layer w0.2: v1(49.6,13.8) 49.667,13.8 49.917,14.05 52.157,14.05 53.132,15.025 62.008,15.025 63.233,13.8 v1(63.3,13.8)
RUN: J2.10 R31.2 U2.26 | length 31.1
  Top Layer w0.2: v1(40.6,5.5) 40.9,5.8 40.9,8.2 41.4,8.7 U2.26 42.6,8.7 42.9,9 v1(42.9,12.5) ; v1(51.825,14.55) 51.875,14.5 53,14.5 R31.2
  Bottom Layer w0.2: v1(40.6,5.5) 40.6,5 42.3,3.3 46.54,3.3 J2.10@48.23,1.61 ; v1(42.9,12.5) 42.9,13.9 43.5,14.5 51.775,14.5 v1(51.825,14.55)
SWCLK: J3.1 U2.24 | length 16.8
  Top Layer w0.2: J3.1 34.6,13.9 34.6,7.8 35.1,7.3 39.9,7.3 40.1,7.5 40.1,8.5 41.1,9.5 U2.24
SWDIO: J3.3 U2.25 | length 12.3
  Top Layer w0.2: J3.3 33.5,8.3 34.9,6.9 40.1,6.9 40.5,7.3 40.5,8.3 41.3,9.1 U2.25
USB_DM: P1.2 R9.1 | length 3.1
  Top Layer w0.2: R9.1 68.3,9.8 68.9,9.8 69.075,9.975 70.765,9.975 P1.2
USB_DP: P1.3 R6.1 | length 3.1
  Top Layer w0.2: R6.1 68.3,10.2 68.734,10.2 68.909,10.375 70.765,10.375 P1.3
VBUS: D1.2 J2.20 P1.1 R2.2 | length 14.8
  Top Layer w0.5: D1.2 67.25,7.15 67.6,7.5 R2.2 ; P1.1 69,9.2 68,8.2 R2.2 ; J2.20@73.63,1.61 72.89,1.61 69.5,5 69.5,6.8 68.8,7.5 R2.2
VSYS: C1.2 D1.1 J2.19 R3.1 R5.2 U1.1 | length 21.8
  Top Layer w0.3: R5.2 57.1,3.6 57.8,2.9 59.7,2.9 60.3,3.5 C1.2
  Top Layer w0.5: C1.2 61.6,3.5 61.9,3.8 v1(62.55,3.8) ; U1.1 v1(62.55,3.8) ; R3.1 62.9,3 62.55,3.35 v1(62.55,3.8) ; D1.1 v1(66.5,3.7) 66.9,3.3 69.9,3.3 71.09,2.11 J2.19@71.09,1.61
  Bottom Layer w0.5: v1(62.55,3.8) 63.25,4.5 65.7,4.5 v1(66.5,3.7)
XIN: C26.1 R13.2 U2.20 Y1.1 | length 7.9
  Top Layer w0.2: Y1.1 39.85,15.25 40.1,15 40.1,12.7 39.9,12.5 C26.1 R13.2 39.9,11.1 U2.20
XOUT: R13.1 R14.2 U2.21 | length 5.2
  Top Layer w0.2: R14.2 R13.1 38.5,10.9 38.7,10.7 U2.21
pads on no net: M1.2 M1.3 M1.4 M1.5 M1.6 M1.9 M1.10 M1.11 M1.12 M1.13 M1.14 M1.19 M1.20 P1.4 U2.35

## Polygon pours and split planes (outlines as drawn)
GND on Top Layer "r" (solid, remove dead copper, pour order 0): 7,0 7,21 75,21 75,0
GND on Bottom Layer "NONET_L-01_P-001" (solid, remove dead copper, pour order 1): 7,0 7,21 75,21 75,0

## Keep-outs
Keep-Out Layer:
  text ".Layer_Name" at 9.398,24.5 h1.52

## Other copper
Top Layer:
  region net 3V3: 59.8,6.2 59.5,6.5 59.5,7.8 59.8,8.1 62.6,8.1 62.9,7.8 62.9,6.4 62.7,6.2
  region net 3V3_EN: 64.1,5.7 64.1,3.7 64.1,2.7 64.5,2.7 65.2,2 65.2,0.3 66.8,0.3 66.8,2.6 65.7,3.7 65.7,5.4 65.4,5.7
  text ".Layer_Name" at 9.398,24.5 h1.52
Bottom Layer:
  region net 3V3: 61.8,6.8 61.9,6.9 61.9,7.8 61.6,8.1 59.8,8.1 59.5,7.8 59.5,7.2 59.8,6.9 60.7,6.9 61,6.6 61.8,6.6
  text ".Layer_Name" at 9.398,24.5 h1.52
Multi-Layer:
  pour cut-out: 71.1,16.2 ccw(c73,16.2) 73,14.3 ccw(c73,16.2) 74.9,16.2 ccw(c73,16.2) 73,18.1 ccw(c73,16.2)
  pour cut-out: 71.1,4.8 ccw(c73,4.8) 73,2.9 ccw(c73,4.8) 74.9,4.8 ccw(c73,4.8) 73,6.7 ccw(c73,4.8)
  pour cut-out: 50.77,2.713 53.38,2.713 53.38,2.5 50.77,2.5
  pour cut-out: 57.89,2.713 60.5,2.713 60.5,2.5 57.89,2.5
  pour cut-out: 71.1,4.894 71.1,2.7 70.9,2.5 71.5,2.5 71.5,4.9
  pour cut-out: 71.1,16.106 71.1,18.3 70.9,18.5 71.5,18.5 71.5,16.1
  pour cut-out: 66.01,18.287 58.39,18.287 58.39,18.5 66.01,18.5
  pour cut-out: 53.3,18.287 45.62,18.287 45.62,18.5 53.3,18.5
  pour cut-out: 40.61,18.287 33,18.287 33,18.5 40.61,18.5
  pour cut-out: 27.91,18.287 25.3,18.287 25.3,18.5 27.91,18.5
  pour cut-out: 25.37,2.713 27.98,2.713 27.98,2.5 25.37,2.5
  pour cut-out: 35.99,2.713 40.6,2.713 40.6,2.5 35.99,2.5

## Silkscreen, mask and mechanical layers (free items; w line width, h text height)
Top Overlay:
  text ".Layer_Name" at 9.398,24.532 h1.52
  text "Rev 1.0" at 0.5,19.5 h1.5
  text "20" at 24.768,18.5 h1.5 r270
  text "1" at 73.8,18.4 h1.5 r270
  text "2" at 70.662,18.219 h1.5 r270
  text "LED" at 68.6,16.7 h1 r270
  text "WizFi360-EVB-Pico" at 29.25,16.575 h1.7
  text "BOOTSEL" at 60.9,13.775 h1
  text "RUN" at 56,13.75 h1
  text "DEBUG" at 31.9,7.8 h1
  text "PWR" at 59,5.6 h1 r270
  text "39" at 70.318,4.2 h1.5 r270
  text "21" at 25,4 h1.5 r270
  text "Made by WIZnet" at 0.5,0 h1.5
Bottom Overlay:
  lines w0.254: 38.25,6 38.25,6.5 ; 58.25,15.45 58.25,14.75 61,14.75 61,15.45
  text ".Layer_Name" at 9.398,24.5 h1.52
  text "GND" at 30.114,15.8 h1.2 r270
  text "GND" at 42.714,15.8 h1.2 r270
  text "GP9" at 45.414,15.8 h1.2 r270
  text "GP8" at 47.914,15.8 h1.2 r270
  text "GP7" at 50.414,15.8 h1.2 r270
  text "GP6" at 53.014,15.8 h1.2 r270
  text "GND" at 55.514,15.8 h1.2 r270
  text "GP5" at 57.814,15.8 h1.2 r270
  text "GP4" at 60.614,15.8 h1.2 r270
  text "GP3" at 63.214,15.8 h1.2 r270
  text "GP2" at 65.714,15.8 h1.2 r270
  text "GND" at 68.114,15.8 h1.2 r270
  text "GP1" at 69.314,15.8 h1.2 r270
  text "GP0" at 70.214,15.8 h1.2 r270
  text "GP13" at 31.914,15.6 h1.2 r270
  text "GP15" at 25.014,15.3 h1.2 r270
  text "GP14" at 27.614,15.3 h1.2 r270
  text "GP12" at 35.214,15.3 h1.2 r270
  text "GP11" at 37.814,15.3 h1.2 r270
  text "GP10" at 40.214,15.3 h1.2 r270
  text "SWCLK" at 38.5,14.264 h1.2
  text "Connected to WizFi360" at 65.5,13.764 h1.2
  text "GND" at 37.25,12.014 h1.2
  text "SWDIO" at 38.25,9.514 h1.2
  text "Connected to WizFi360" at 44.25,6.764 h1.2
  text "GP20" at 37.764,3 h1.2 r270
  text "GP21" at 40.264,3 h1.2 r270
  text "GND" at 42.764,3 h1.2 r270
  text "GP16" at 25.014,2.9 h1.2 r270
  text "GP17" at 27.514,2.9 h1.2 r270
  text "GND" at 30.014,2.9 h1.2 r270
  text "GP18" at 32.614,2.9 h1.2 r270
  text "GP19" at 35.114,2.9 h1.2 r270
  text "RUN" at 48.014,2.9 h1.2 r270
  text "GP26_A0" at 50.412,2.9 h1.2 r270
  text "AGND" at 55.414,2.9 h1.2 r270
  text "GP27_A1" at 52.836,2.861 h1.2 r270
  text "GP28_A2" at 58.036,2.861 h1.2 r270
  text "ADC_VREF" at 60.536,2.861 h1.2 r270
  text "3V3" at 63.014,2.8 h1.2 r270
  text "3V3_EN" at 65.712,2.8 h1.2 r270
  text "GND" at 68.114,2.8 h1.2 r270
  text "VSYS" at 69.414,2.8 h1.2 r270
  text "VBUS" at 70.314,2.8 h1.2 r270
  text "GP22" at 45.264,2.75 h1.2 r270
Top Paste:
  text ".Layer_Name" at 9.398,24.5 h1.52
Bottom Paste:
  text ".Layer_Name" at 9.398,24.5 h1.52
Top Solder:
  text ".Layer_Name" at 9.398,24.5 h1.52
Bottom Solder:
  text ".Layer_Name" at 9.398,24.5 h1.52
Drill Guide:
  text ".Layer_Name" at 9.398,24.5 h1.52
Mechanical 2:
  lines w0.127: 79.85,12 104,12 ; 78.85,4.775 ccw(c79.561,4.775) 79.561,4.064 104.239,4.064 ccw(c104.239,4.775) 104.95,4.775 104.95,20.503 ccw(c104.239,20.503) 104.239,21.214 79.561,21.214 ccw(c79.561,20.503) 78.85,20.503 78.85,4.775
  lines w0.2: 0,0 75,0 75,21 0,21 0,0
  text "BOARD NAME : WizFi360-EVB-Pico" at 0,35.676 h1.52
  text "VERSION : V100" at 0,32.882 h1.52
  text "SIZE : 75mmX21mmX1.0T" at 0,30.088 h1.52
  text "GERBER DATE : 2022.03.31" at 0,27.294 h1.52
  text "LAYER :" at 0,24.5 h1.52
  text "Layer Stack Up Detail for:" at 80.323,18.606 h1.02
  text "WizFi360-EVB-Pico_V100.PcbDoc" at 80.196,16.193 h1
  text "Layer Name : 2L  1.0T" at 80.323,13.018 h1.02
  text "Top Layer" at 80.196,9.335 h1.52
  text "Bottom Layer" at 80.196,6.334 h1.52
  text "KS Technology artwork" at 78.85,0 h5.08
Drill Drawing:
  text ".Layer_Name" at 9.398,24.5 h1.52
  text ".Legend" at 79.85,22.75 h1.02

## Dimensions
-0.5,0 to -0.5,21 on Mechanical 2
0,-0.4 to 75,-0.5 on Mechanical 2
